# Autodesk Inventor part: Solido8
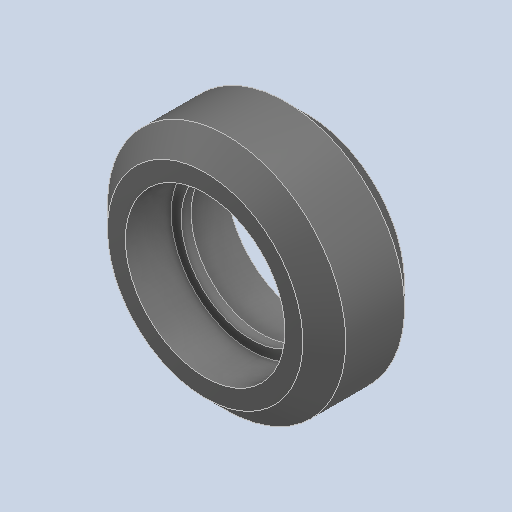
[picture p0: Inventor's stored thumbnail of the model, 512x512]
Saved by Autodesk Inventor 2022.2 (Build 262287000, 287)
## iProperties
Created: 2024-10
Part Number: Solido8
Material: Generico
Document SubType Name: Modeling
Designer: 18907419
Density: 1 g/cm^3
Appearance: Default
Author: 18907419
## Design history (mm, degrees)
feature "Solido8"
node "Solido1"
